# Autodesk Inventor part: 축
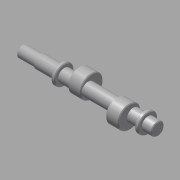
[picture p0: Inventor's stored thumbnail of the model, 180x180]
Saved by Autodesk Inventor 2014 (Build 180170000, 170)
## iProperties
Created: 2013-02
Part Number: 축
Document SubType Name: Modeling
Designer: 한국산업디자인학원[gmhk.co.kr]
Density: 7.86 g/cm^3
Material: 강철, 연강
Mass: 458.535 g
Surface Area: 143.366 cm^2
Volume: 58.3377 cm^3
Appearance: 강철
Author: 한국산업디자인학원[gmhk.co.kr]
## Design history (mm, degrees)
sketch "스케치2"
  geometry: L1 (-58, 84.5)-(-58, 15.5) reference; L2 (58, 15.5)-(58, 84.5) reference; L3 (-85, 25.774)-(-85, 74.226) reference; L4 (70, 84.185)-(70, 15.815) reference; L5 (71, 50)-(-109, 50); L6 (69.4, 58.5)-(58.6, 58.5) reference; L7 (71, 50)-(71, 58.5); L8 (71, 58.5)-(58, 58.5); L9 (58, 58.5)-(58, 63); L10 (58, 63)-(53, 63); L11 (53, 63)-(53, 58.5); L12 (53, 58.5)-(-53, 58.5); L13 (-53, 58.5)-(-53, 63); L14 (-53, 63)-(-58, 63); L15 (-58, 63)-(-58, 58.5); L16 (-58, 58.5)-(-85, 58.5); L17 (-85, 58.5)-(-85, 57.5); L18 (-85, 57.5)-(-109, 57.5); L19 (-109, 57.5)-(-109, 50); L20 (-30, 102.5)-(-30, 50); L21 (30, 102.5)-(30, 50); L22 (-50, 102.5)-(-10, 102.5) reference; L23 (10, 102.5)-(50, 102.5) reference; 2 further points
  constraints: 34 end point, 10 perpendicular, 9 point on line, 5 collinear, 3 midpoint, 3 parallel, 1 horizontal, 2 other
  dimensions: "d0" = 1 distance between parallel lines of L7 L4; "d1" = 26 diameter of L10 L5; "d2" = 5 distance of L9.end L10.end; "d3" = 5 distance of L13.end L14.end (= d2); "d4" = 180 distance of L5.start L5.end; "d5" = 15 diameter of L18 L5
  node "참조1"
  node "참조2"
  node "참조3"
  node "참조4"
  node "참조7"
  node "참조8"
revolve "회전1" stored, may be unused: angle "d6" = 90 deg
node "작업 평면1"
sketch "스케치3"
  geometry: C1 r 8.5 at (52.5, 0) reference; C2 r 15 at (47.5, 0); 1 further point
  constraints: 1 centre point, 1 horizontal alignment
  dimensions: "d8" = 5 distance of C1.centre C2.centre; "d9" = 30 diameter of C2
extrude "돌출1" join sketch "스케치3" stored distance "d10" = 17; taper "d11" = 0 deg
node "작업 평면2"
sketch "스케치4"
  geometry: C1 r 8.5 at (52.5, 0) reference; C2 r 15 at (57.5, 0); 1 further point
  constraints: 1 centre point, 1 horizontal alignment
  dimensions: "d13" = 5 distance of C2.centre C1.centre; "d14" = 30 diameter of C2
extrude "돌출2" join sketch "스케치4" stored distance "d15" = 17; taper "d16" = 0 deg
chamfer "모따기1" distance "d17" = 1; stored, may be unused: second distance "d18" = 2, angle "d19" = 45 deg
node "작업 평면3"
sketch "스케치5"
  geometry: L1 (12, 6.5)-(12, -6.5) reference; L2 (12, 2.5)-(-5.5, 2.5); L3 (-5.5, -2.5)-(12, -2.5); A1 r 2.5 centre (-5.5, 0) between (-5.5, 2.5) and (-5.5, -2.5); 2 further points
  constraints: 4 end point, 2 point on circle, 2 point on line, 2 tangent, 1 centre point, 1 horizontal alignment, 1 midpoint, 1 parallel, 1 perpendicular
  dimensions: "d20" = 5 distance between parallel lines of L3 L2; "d21" = 20 dimension on A1 L1
extrude "돌출3" cut sketch "스케치5" distance "d22" = 3; taper "d23" = 0 deg
chamfer "모따기2" distance "d24" = 1; stored, may be unused: second distance "d25" = 2, angle "d26" = 45 deg
node "솔리드1"
node "투영된 루프1"
node "투영된 루프2"
other parameters: "d7" = 0, "d12" = 0
